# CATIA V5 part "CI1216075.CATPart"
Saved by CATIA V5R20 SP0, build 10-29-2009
Part number: CI1216075
Bounding box of the stored display mesh (mm): x -15 to 15, y -11.764 to 99, z -17.351 to 17.399
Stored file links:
  C:\Users\Raffaele\Desktop\3D X SITO CF\BOLEX\19-INCLINED ASSEMBLY REF_CI\CI1216075.CATPart

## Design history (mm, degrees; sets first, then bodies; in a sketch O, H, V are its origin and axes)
Set1
  DatumSurface1 to DatumSurface16 "MANIFOLD_SOLID_BREP #381"
  DatumSurface17 to DatumSurface39 "MANIFOLD_SOLID_BREP #1106"
Body1 (main body)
